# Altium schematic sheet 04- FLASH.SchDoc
size A3
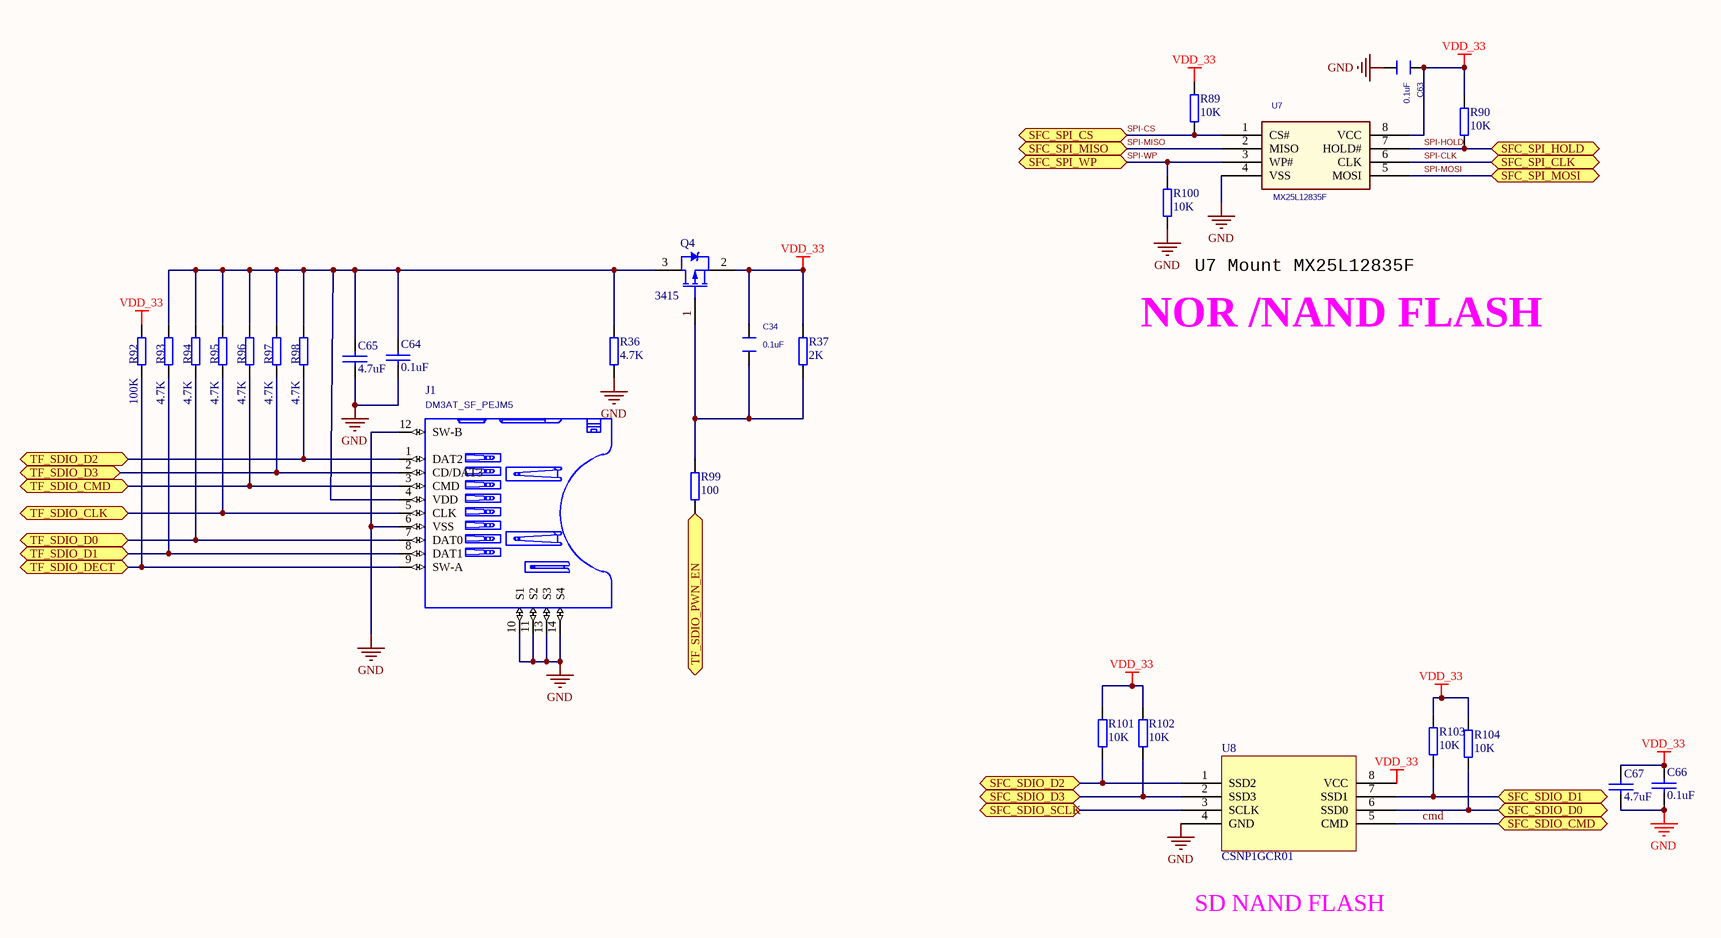
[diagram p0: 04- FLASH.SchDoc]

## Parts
C34  0.1uF  [C0402]
C63  0.1uF  [C0402]
C64  0.1uF  [C0402]
C65  4.7uF  [C0402]
C66  0.1uF  [C0402]
C67  4.7uF  [C0402]
J1  DEVICE: DM3AT_SF_PEJM5  [SD_CARD-Push]  (hidden comment: MMC8S4)
Q4  3415  [SOT-23]
R36  4.7K  [R0402]
R37  2K  [R0402]
R89  10K  [R0402]
R90  10K  [R0402]
R92  100K  [R0402]
R93  4.7K  [R0402]
R94  4.7K  [R0402]
R95  4.7K  [R0402]
R96  4.7K  [R0402]
R97  4.7K  [R0402]
R98  4.7K  [R0402]
R99  100  [R0402]
R100  10K  [R0402]
R101  10K  [R0402]
R102  10K  [R0402]
R103  10K  [R0402]
R104  10K  [R0402]
U7  MX25L12835F  [SOP-8M(PAD)]
U8  CSNP1GCR01  [CSNP1GCR01]

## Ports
SFC_SDIO_CMD (bidir), SFC_SDIO_D0 (bidir), SFC_SDIO_D1 (bidir), SFC_SDIO_D2 (bidir), SFC_SDIO_D3 (bidir), SFC_SDIO_SCLK (bidir), SFC_SPI_CLK (bidir), SFC_SPI_CS (bidir), SFC_SPI_HOLD (bidir), SFC_SPI_MISO (bidir), SFC_SPI_MOSI (bidir), SFC_SPI_WP (bidir), TF_SDIO_CLK (bidir), TF_SDIO_CMD (bidir), TF_SDIO_D0 (bidir), TF_SDIO_D1 (bidir), TF_SDIO_D2 (bidir), TF_SDIO_D3 (bidir), TF_SDIO_DECT (bidir), TF_SDIO_PWN_EN (bidir)

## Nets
GND: C63.1 C64.2 C65.2 C66.2 C67.2 J1.6(VSS) J1.10(S1) J1.11(S2) J1.12(SW-B) J1.13(S3) J1.14(S4) R36.1 R100.2 U7.4(VSS) U8.4(GND)
VDD_33: C34.2 C63.2 C66.1 C67.1 Q4.2(S) R37.2 R89.1 R90.1 R92.2 R101.1 R102.1 R103.1 R104.1 U7.8(VCC) U8.8(VCC)
cmd: U8.5(CMD) ; port SFC_SDIO_CMD
SFC_SDIO_D0: R104.2 U8.6(SSD0) ; port SFC_SDIO_D0
SFC_SDIO_D1: R103.2 U8.7(SSD1) ; port SFC_SDIO_D1
SFC_SDIO_D2: R101.2 U8.1(SSD2) ; port SFC_SDIO_D2
SFC_SDIO_D3: R102.2 U8.2(SSD3) ; port SFC_SDIO_D3
SFC_SDIO_SCLK: U8.3(SCLK) ; port SFC_SDIO_SCLK
SPI-CLK: U7.6(CLK) ; port SFC_SPI_CLK
SPI-CS: R89.2 U7.1(CS#) ; port SFC_SPI_CS
SPI-HOLD: R90.2 U7.7(HOLD#) ; port SFC_SPI_HOLD
SPI-MISO: U7.2(MISO) ; port SFC_SPI_MISO
SPI-MOSI: U7.5(MOSI) ; port SFC_SPI_MOSI
SPI-WP: R100.1 U7.3(WP#) ; port SFC_SPI_WP
TF_SDIO_CLK: J1.5(CLK) R95.1 ; port TF_SDIO_CLK
TF_SDIO_CMD: J1.3(CMD) R96.1 ; port TF_SDIO_CMD
TF_SDIO_D0: J1.7(DAT0) R94.1 ; port TF_SDIO_D0
TF_SDIO_D1: J1.8(DAT1) R93.1 ; port TF_SDIO_D1
TF_SDIO_D2: J1.1(DAT2) R98.1 ; port TF_SDIO_D2
TF_SDIO_D3: J1.2(CD/DAT3) R97.1 ; port TF_SDIO_D3
TF_SDIO_DECT: J1.9(SW-A) R92.1 ; port TF_SDIO_DECT
TF_SDIO_PWN_EN: R99.1 ; port TF_SDIO_PWN_EN
NetC34_1: C34.1 Q4.1(G) R37.1 R99.2
NetC64_1: C64.1 C65.1 J1.4(VDD) Q4.3(D) R36.2 R93.2 R94.2 R95.2 R96.2 R97.2 R98.2

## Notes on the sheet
- (near R100) U7 Mount MX25L12835F
- NOR /NAND FLASH
- SD NAND FLASH

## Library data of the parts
C34 C63 = CAPACITOR_Dup1: PAGE: 7
C64-C67 = 电容: Capacitor
J1 = MMC8S4: PARTS: 1; LEVEL: STD; PKG_TYPE: HSDC10-1614B; CODE: 1414G006; OriginalSymbolOrigin: (0,0); %208%%161%%192%%224%%195%%251%%179%%198%: 板卡座; COMPONENT_HIGH_MAX: 1.83MM; %195%%232%%202%%246%: 板卡座-弯母-10-PUSH-PUSH MICROSD-表贴PAD
Q4 = PMOS-2: P-Channel Power MOSFET; Note: Pin 4 not drawn and electrically connected to Pin 2.
R36 R37 R89 R90 R92-R104 = 电阻Ω: Resistor
U7 = SPI-NOR-SO8: PAGE: 7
